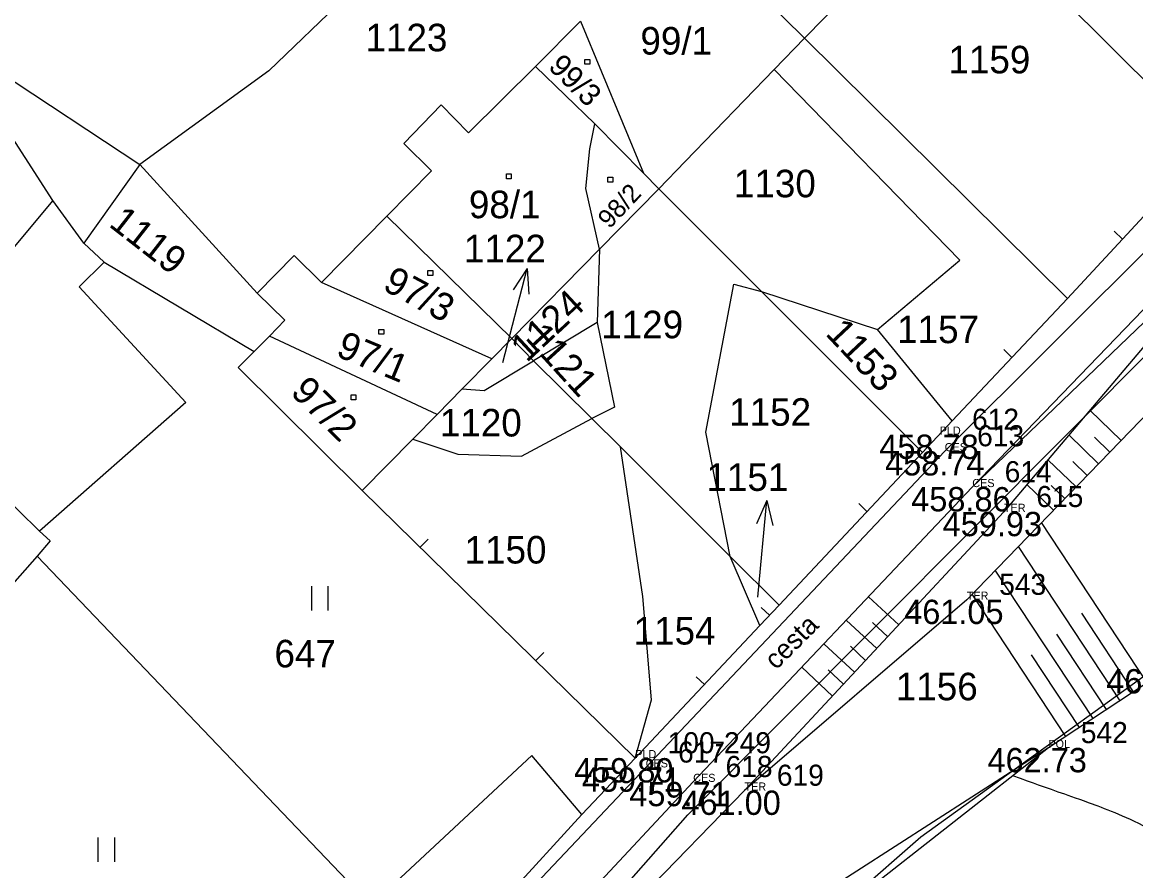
# Model space of a CAD drawing. Extents: x -604848 to -603227, y -1111879 to -1109838.
# Drawn here: x -603411.4 to -603342.6, y -1110345.8 to -1110293.4 of the extents above; entities that cross this region are included whole.
import ezdxf

# ---------------------------------------------------------------- set-up
doc = ezdxf.new("R2010")
doc.units = 0
for name, color, linetype in [('1', 7, 'Continuous'), ('10', 7, 'Continuous'), ('14', 7, 'Continuous'), ('15', 7, 'Continuous'), ('18', 7, 'Continuous'), ('19', 7, 'Continuous'), ('20', 7, 'Continuous'), ('23', 7, 'Continuous'), ('25', 7, 'Continuous'), ('4', 7, 'Continuous'), ('7', 7, 'Continuous'), ('8', 7, 'Continuous'), ('9', 7, 'Continuous'), ('Default', 7, 'Continuous')]:
    doc.layers.add(name, color=color, linetype=linetype)

# ---------------------------------------------------------------- blocks, each defined once
blk = doc.blocks.new('Z3060')
at = {"layer": '23'}
for p, q in [((-0.5, 0), (-0.5, 1.5)), ((0.5, 1.5), (0.5, 0))]:
    blk.add_line(p, q, dxfattribs=at)
blk = doc.blocks.new('Z402')
at = {"layer": '25'}
for p, q in [((-0.1, 0.1), (0.2, 0.1)), ((-0.1, -0.2), (-0.1, 0.1)), ((0.2, 0.1), (0.2, -0.2)), ((0.2, -0.2), (-0.1, -0.2))]:
    blk.add_line(p, q, dxfattribs=at)
blk = doc.blocks.new('POINT_DISPLAY')
at = {"layer": 'Default'}
blk.add_line((0, 0), (0, 0), dxfattribs=at)
blk = doc.blocks.new('Z802')
at = {"layer": '1'}
for p, q in [((-3, -0.001), (3, 0)), ((3, 0), (1.5, 0.5)), ((3, 0), (1.5, -0.5))]:
    blk.add_line(p, q, dxfattribs=at)
blk = doc.blocks.new('Z210')
at = {"layer": '4'}
blk.add_line((0, 0), (0, 0.7), dxfattribs=at)

msp = doc.modelspace()

# ---------------------------------------------------------------- linework, layer by layer
at = {"layer": '1'}
for p, q in [((-603373.09, -1110274.25), (-603396.13, -1110296.39)), ((-603353.98, -1110285.12), (-603363.06, -1110294.37)), ((-603338.06, -1110300.99), (-603353.98, -1110285.12)), ((-603424.91, -1110288.46), (-603404.1, -1110302.17)), ((-603366.48, -1110290.99), (-603363.06, -1110294.37)), ((-603379.67, -1110296.12), (-603376.88, -1110293.33)), ((-603376.88, -1110293.33), (-603373.01, -1110302.71)), ((-603363.06, -1110294.37), (-603364.94, -1110296.31)), ((-603363.06, -1110294.37), (-603346.82, -1110310.44)), ((-603409.47, -1110304.4), (-603414.6, -1110296.45)), ((-603396.13, -1110296.39), (-603404.1, -1110302.17)), ((-603379.67, -1110296.12), (-603383.8, -1110300.23)), ((-603376.01, -1110299.66), (-603379.67, -1110296.12)), ((-603370.43, -1110302), (-603364.94, -1110296.31)), ((-603353.48, -1110308.08), (-603364.94, -1110296.31)), ((-603385.49, -1110298.5), (-603387.8, -1110300.88)), ((-603383.8, -1110300.23), (-603385.49, -1110298.5)), ((-603376.31, -1110301.21), (-603376.01, -1110299.66)), ((-603373.01, -1110302.71), (-603376.01, -1110299.66)), ((-603387.8, -1110300.88), (-603386.09, -1110302.57)), ((-603376.56, -1110303.66), (-603376.31, -1110301.21)), ((-603346.82, -1110310.44), (-603338.06, -1110300.99)), ((-603372.05, -1110303.68), (-603370.43, -1110302)), ((-603404.1, -1110302.17), (-603407.55, -1110307.03)), ((-603404.1, -1110302.17), (-603396.86, -1110310.11)), ((-603386.09, -1110302.57), (-603388.84, -1110305.36)), ((-603373.01, -1110302.71), (-603372.05, -1110303.68)), ((-603375.72, -1110307.41), (-603376.56, -1110303.66)), ((-603372.05, -1110303.68), (-603375.72, -1110307.41)), ((-603372.05, -1110303.68), (-603365.72, -1110310.01)), ((-603409.47, -1110304.4), (-603432.14, -1110331.48)), ((-603407.55, -1110307.03), (-603409.47, -1110304.4)), ((-603392.87, -1110309.45), (-603388.84, -1110305.36)), ((-603388.84, -1110305.36), (-603381.13, -1110312.91)), ((-603407.55, -1110307.03), (-603406.29, -1110308.2)), ((-603381.13, -1110312.91), (-603375.72, -1110307.41)), ((-603375.72, -1110307.41), (-603375.86, -1110311.93)), ((-603406.29, -1110308.2), (-603407.85, -1110309.73)), ((-603406.29, -1110308.2), (-603397.04, -1110313.72)), ((-603396.86, -1110310.11), (-603394.56, -1110307.79)), ((-603394.56, -1110307.79), (-603392.87, -1110309.45)), ((-603358.56, -1110312.36), (-603353.48, -1110308.08)), ((-603370.26, -1110342.3), (-603336.36, -1110308.3)), ((-603382.36, -1110314.16), (-603392.87, -1110309.45)), ((-603369.16, -1110318.69), (-603367.43, -1110309.56)), ((-603367.43, -1110309.56), (-603365.72, -1110310.01)), ((-603407.85, -1110309.73), (-603401.25, -1110316.87)), ((-603395.15, -1110311.79), (-603396.86, -1110310.11)), ((-603355.78, -1110319.94), (-603365.72, -1110310.01)), ((-603365.72, -1110310.01), (-603358.56, -1110312.36)), ((-603346.82, -1110310.44), (-603353.94, -1110317.99)), ((-603396.1, -1110312.76), (-603395.15, -1110311.79)), ((-603375.86, -1110311.93), (-603379.8, -1110314.3)), ((-603375.86, -1110311.93), (-603374.8, -1110317.15)), ((-603353.94, -1110317.99), (-603358.56, -1110312.36)), ((-603396.1, -1110312.76), (-603397.04, -1110313.72)), ((-603385.74, -1110317.6), (-603396.1, -1110312.76)), ((-603381.13, -1110312.91), (-603382.36, -1110314.16)), ((-603379.8, -1110314.3), (-603381.13, -1110312.91)), ((-603397.04, -1110313.72), (-603398.02, -1110314.71)), ((-603382.36, -1110314.16), (-603384.19, -1110316.02)), ((-603382.83, -1110316.12), (-603379.8, -1110314.3)), ((-603376.18, -1110317.85), (-603379.8, -1110314.3)), ((-603398.02, -1110314.71), (-603390.36, -1110322.29)), ((-603384.19, -1110316.02), (-603385.74, -1110317.6)), ((-603384.19, -1110316.02), (-603382.83, -1110316.12)), ((-603401.25, -1110316.87), (-603410.28, -1110324.8)), ((-603374.8, -1110317.15), (-603376.18, -1110317.85)), ((-603385.74, -1110317.6), (-603387.24, -1110319.12)), ((-603380.53, -1110320.18), (-603376.18, -1110317.85)), ((-603374.43, -1110319.59), (-603376.18, -1110317.85)), ((-603353.94, -1110317.99), (-603355.78, -1110319.94)), ((-603387.24, -1110319.12), (-603390.36, -1110322.29)), ((-603387.24, -1110319.12), (-603384.47, -1110320.05)), ((-603367.64, -1110326.36), (-603369.16, -1110318.69)), ((-603374.43, -1110319.59), (-603367.64, -1110326.36)), ((-603373.04, -1110328.83), (-603374.43, -1110319.59)), ((-603384.47, -1110320.05), (-603380.53, -1110320.18)), ((-603355.78, -1110319.94), (-603364.63, -1110329.36)), ((-603413.11, -1110322.03), (-603410.28, -1110324.8)), ((-603390.36, -1110322.29), (-603373.51, -1110338.81)), ((-603409.63, -1110325.41), (-603410.43, -1110326.34)), ((-603410.28, -1110324.8), (-603409.63, -1110325.41)), ((-603329.76, -1110324.86), (-603355.87, -1110343.69)), ((-603410.43, -1110326.34), (-603415.89, -1110332.51)), ((-603389.83, -1110347.88), (-603410.43, -1110326.34)), ((-603364.63, -1110329.36), (-603367.64, -1110326.36)), ((-603365.82, -1110330.63), (-603367.64, -1110326.36)), ((-603372.5, -1110335.21), (-603373.04, -1110328.83)), ((-603364.63, -1110329.36), (-603365.82, -1110330.63)), ((-603365.82, -1110330.63), (-603373.51, -1110338.81)), ((-603373.51, -1110338.81), (-603372.5, -1110335.21)), ((-603379.89, -1110338.64), (-603389.83, -1110347.88)), ((-603376.8, -1110342.29), (-603379.89, -1110338.64)), ((-603376.8, -1110342.29), (-603373.51, -1110338.81)), ((-603392.03, -1110358.87), (-603376.8, -1110342.29)), ((-603382.27, -1110355.9), (-603370.26, -1110342.3)), ((-603355.87, -1110343.69), (-603372.97, -1110358.59))]:
    msp.add_line(p, q, dxfattribs=at)
at = {"layer": '10'}
for p, q in [((-603340.627, -1110333.317), (-603348.003, -1110338.183)), ((-603348.003, -1110338.183), (-603362.214, -1110349.319))]:
    msp.add_line(p, q, dxfattribs=at)
at = {"layer": '4'}
for p, q in [((-603354.402, -1110319.865), (-603337.675, -1110303.2)), ((-603336.348, -1110305.122), (-603352.703, -1110322.083)), ((-603372.866, -1110339.384), (-603354.402, -1110319.865)), ((-603352.703, -1110322.083), (-603369.934, -1110340.276)), ((-603382.136, -1110349.18), (-603372.866, -1110339.384)), ((-603369.934, -1110340.276), (-603380.338, -1110351.389))]:
    msp.add_line(p, q, dxfattribs=at)
at = {"layer": '7'}
for p, q in [((-603335.544, -1110305.621), (-603352.703, -1110322.083)), ((-603335.544, -1110305.621), (-603350.746, -1110323.613)), ((-603353.042, -1110329.034), (-603338.411, -1110313.943)), ((-603350.746, -1110323.613), (-603366.767, -1110340.813)), ((-603353.042, -1110329.034), (-603366.767, -1110340.813)), ((-603348.003, -1110338.183), (-603363.392, -1110348.07)), ((-603366.767, -1110340.813), (-603378.795, -1110353.151))]:
    msp.add_line(p, q, dxfattribs=at)
msp.add_open_spline([(-603327.118, -1110334.726), (-603329.805, -1110337.428), (-603332.491, -1110340.13), (-603335.181, -1110342.83), (-603337.781, -1110345.44), (-603342.659, -1110342.576), (-603346.131, -1110341.347), (-603347.488, -1110340.867), (-603348.845, -1110340.386), (-603350.202, -1110339.906)], degree=3, dxfattribs=at)
at = {"layer": '8'}
for p, q in [((-603343.513, -1110319.205), (-603345.442, -1110317.335)), ((-603344.905, -1110320.641), (-603346.736, -1110318.866)), ((-603344.209, -1110319.923), (-603345.149, -1110319.012)), ((-603346.297, -1110322.077), (-603348.03, -1110320.398)), ((-603345.601, -1110321.359), (-603346.492, -1110320.496)), ((-603347.69, -1110323.513), (-603349.324, -1110321.929)), ((-603346.993, -1110322.795), (-603347.835, -1110321.979)), ((-603341.91, -1110334.163), (-603348.431, -1110324.278)), ((-603343.58, -1110335.265), (-603349.857, -1110325.749)), ((-603345.249, -1110336.366), (-603351.283, -1110327.22)), ((-603357.241, -1110330.585), (-603359.108, -1110328.846)), ((-603346.919, -1110337.467), (-603352.709, -1110328.69)), ((-603342.745, -1110334.714), (-603345.945, -1110329.864)), ((-603358.604, -1110332.049), (-603360.483, -1110330.298)), ((-603357.922, -1110331.317), (-603358.859, -1110330.444)), ((-603344.415, -1110335.815), (-603347.492, -1110331.15)), ((-603359.967, -1110333.512), (-603361.859, -1110331.75)), ((-603359.285, -1110332.78), (-603360.228, -1110331.902)), ((-603346.084, -1110336.917), (-603349.04, -1110332.436)), ((-603361.33, -1110334.976), (-603363.234, -1110333.202)), ((-603360.648, -1110334.244), (-603361.597, -1110333.36))]:
    msp.add_line(p, q, dxfattribs=at)

# ---------------------------------------------------------------- block references
at = {"layer": '1'}
for p, xscale, yscale, rotation in [((-603380.937, -1110311.497), 0.9999979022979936, 0.9999979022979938, 75.60014981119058), ((-603365.663, -1110325.896), 0.9999953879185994, 0.9999953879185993, 84.60012833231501)]:
    msp.add_blockref('Z802', p, dxfattribs=dict(at, xscale=xscale, yscale=yscale, rotation=rotation))
at = {"layer": '18'}
for p in [(-603354.716, -1110318.846), (-603354.402, -1110319.865), (-603352.703, -1110322.083), (-603350.746, -1110323.613), (-603353.042, -1110329.034), (-603348.003, -1110338.183), (-603373.51, -1110338.81), (-603372.866, -1110339.384), (-603369.934, -1110340.276), (-603366.767, -1110340.813)]:
    msp.add_blockref('POINT_DISPLAY', p, dxfattribs=at)
at = {"layer": '23'}
for p in [(-603392.98, -1110329.7), (-603406.16, -1110345.21)]:
    msp.add_blockref('Z3060', p, dxfattribs=at)
at = {"layer": '25'}
for p in [(-603376.52, -1110295.79), (-603381.36, -1110302.86), (-603375.1, -1110303.06), (-603386.21, -1110308.82), (-603389.23, -1110312.45), (-603390.95, -1110316.49)]:
    msp.add_blockref('Z402', p, dxfattribs=at)
at = {"layer": '4'}
for p, xscale, yscale, rotation in [((-603343.42, -1110306.773), 0.9999974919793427, 0.9999974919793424, 47.169918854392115), ((-603350.25, -1110314.077), 0.9999961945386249, 0.999996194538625, 46.67893821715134), ((-603359.203, -1110323.584), 0.9999973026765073, 0.9999973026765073, 46.7870879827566), ((-603386.789, -1110325.79), 0.9999944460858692, 0.999994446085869, -44.43344336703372), ((-603365.225, -1110329.995), 0.9999965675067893, 0.9999965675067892, 46.8627803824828), ((-603379.649, -1110332.791), 0.9999944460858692, 0.999994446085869, -44.43344336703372), ((-603369.244, -1110334.272), 0.9999970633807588, 0.9999970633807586, 46.76840207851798)]:
    msp.add_blockref('Z210', p, dxfattribs=dict(at, xscale=xscale, yscale=yscale, rotation=rotation))

# ---------------------------------------------------------------- texts
at = {"layer": '14'}
for s, p in [('1123', (-603390.164, -1110295.19)), ('1159', (-603354.174, -1110296.55)), ('1130', (-603367.42, -1110304.2)), ('1122', (-603384.085, -1110308.209)), ('1129', (-603375.611, -1110312.9)), ('1157', (-603357.341, -1110313.2)), ('1152', (-603367.709, -1110318.298)), ('1120', (-603385.573, -1110318.96)), ('1151', (-603369.114, -1110322.317)), ('1150', (-603384.047, -1110326.8)), ('1154', (-603373.61, -1110331.8)), ('647', (-603395.784, -1110333.21)), ('1156', (-603357.424, -1110335.24))]:
    msp.add_text(s, height=1.7, dxfattribs=at).set_placement(p)
for s, rotation, p in [('1119', 322.00227, (-603406.075, -1110305.946)), ('1124', 42.87276, (-603380.215, -1110314.442)), ('1121', 312.38451, (-603380.356, -1110312.904)), ('1153', 313.236, (-603361.825, -1110312.654))]:
    msp.add_text(s, height=1.7, rotation=rotation, dxfattribs=at).set_placement(p)
at = {"layer": '15'}
for s, p in [('99/1', (-603373.19, -1110295.39)), ('98/1', (-603383.78, -1110305.49))]:
    msp.add_text(s, height=1.7, dxfattribs=at).set_placement(p)
for s, height, rotation, p in [('99/3', 1.36, 315.10773, (-603378.94, -1110296.2)), ('98/2', 1.14, 46.68129, (-603375.1, -1110306.19)), ('97/3', 1.7, 331.74252, (-603389.18, -1110309.87)), ('97/1', 1.7, 337.35753, (-603392.06, -1110313.97)), ('97/2', 1.7, 315.58518, (-603394.86, -1110316.3))]:
    msp.add_text(s, height=height, rotation=rotation, dxfattribs=at).set_placement(p)
at = {"layer": '18'}
for s, p in [('PLD', (-603354.716, -1110318.846)), ('CES', (-603354.402, -1110319.865)), ('CES', (-603352.703, -1110322.083)), ('TER', (-603350.746, -1110323.613)), ('TER', (-603353.042, -1110329.034)), ('POL', (-603348.003, -1110338.183)), ('PLD', (-603373.51, -1110338.81)), ('CES', (-603372.866, -1110339.384)), ('CES', (-603369.934, -1110340.276)), ('TER', (-603366.767, -1110340.813))]:
    msp.add_text(s, height=0.5, dxfattribs=at).set_placement(p)
at = {"layer": '19'}
for s, p in [('612', (-603352.716, -1110318.546)), ('613', (-603352.402, -1110319.565)), ('614', (-603350.703, -1110321.783)), ('615', (-603348.746, -1110323.313)), ('543', (-603351.042, -1110328.734)), ('542', (-603346.003, -1110337.883)), ('100-249', (-603371.51, -1110338.51)), ('617', (-603370.866, -1110339.084)), ('618', (-603367.934, -1110339.976)), ('619', (-603364.767, -1110340.513))]:
    msp.add_text(s, height=1.3, dxfattribs=at).set_placement(p)
at = {"layer": '20'}
for s, p in [('458.78 ', (-603358.44, -1110320.346)), ('458.74 ', (-603358.085, -1110321.365)), ('458.86 ', (-603356.474, -1110323.583)), ('459.93 ', (-603354.529, -1110325.113)), ('461.05 ', (-603356.905, -1110330.534)), ('462.59 ', (-603344.434, -1110334.817)), ('462.73 ', (-603351.762, -1110339.683)), ('459.80 ', (-603377.284, -1110340.31)), ('459.71 ', (-603376.809, -1110340.884)), ('459.71 ', (-603373.877, -1110341.776)), ('461.00 ', (-603370.659, -1110342.313))]:
    msp.add_text(s, height=1.5, dxfattribs=at).set_placement(p)
at = {"layer": '9'}
msp.add_text('cesta', height=1.2, rotation=45, dxfattribs=at).set_placement((-603364.811, -1110333.405))

doc.saveas('drawing.dxf')
